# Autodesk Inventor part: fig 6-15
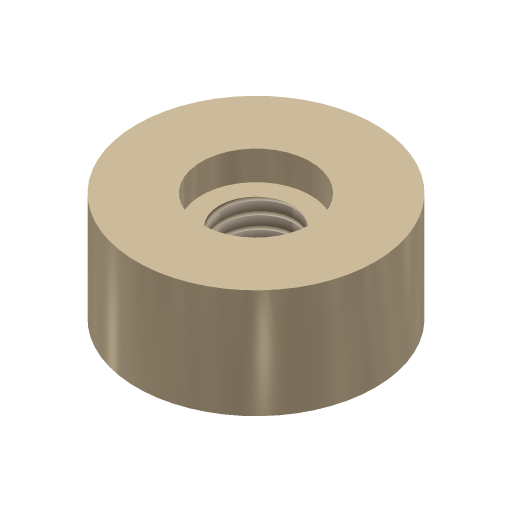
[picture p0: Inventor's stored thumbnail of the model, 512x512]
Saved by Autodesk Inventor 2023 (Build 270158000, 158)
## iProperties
Created: 2001-11
Part Number: fig 6-15
Document SubType Name: Modeling
Designer: Renu Muthoo
Density: 1 g/cm^3
Material: Generic
Appearance: Metal-Titanium (Polished)
Control State: 0
Master: False
Checked Out: False
Shininess: 65.0
Angle Display Precision: 2
Document Length Units: 11269
Document Angle Units: 11279
Document Time Units: 11290
Document Mass Units: 11283
Document Length Units Precision: 3
Document Angle Units Precision: 2
Density: 0.0
Volumn: 0.0
Area: 0.0
PropertySet Name: Model Information
Author: Renu Muthoo
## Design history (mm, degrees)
sketch "Sketch1"
  geometry: C1 r 16.401 at (0, 0)
  constraints: 1 centre point
extrude "Extrusion1" new body sketch "Sketch1" distance "d0" = 15; taper "d1" = 0 deg
hole "Hole3" diameter "d18" = 10.106; stored, may be unused: countersink angle "d22" = 90 deg, drill point angle "d24" = 118 deg; dims "d16" = 10, "d17" = 10, "d19" = 6, "d20" = 15, "d21" = 4, "d23" = 10
body "Solid1"
